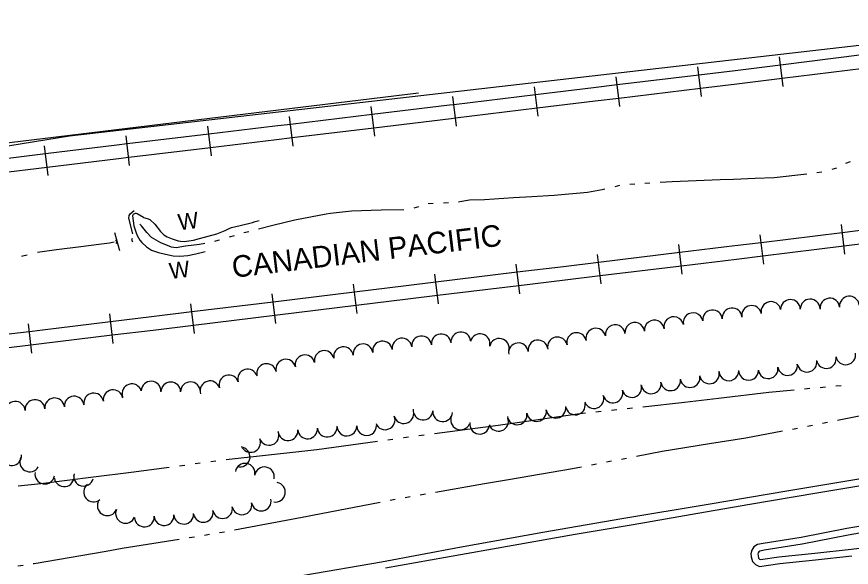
# Model space of a CAD drawing. Extents: x 589250 to 1188077, y 162953 to 363065.
# Drawn here: x 591882.9 to 592191.9, y 174605.4 to 174809.3 of the extents above; entities that cross this region are included whole.
import ezdxf

# ---------------------------------------------------------------- set-up
doc = ezdxf.new("R2010")
doc.units = 0
for name, color, linetype in [('E_DRN', 7, 'Continuous'), ('E_LAND_TreeLine_P', 7, 'Continuous'), ('E_MAP_Limits', 7, 'Continuous'), ('E_RDWY', 7, 'Continuous'), ('E_RDWY_C_and_G', 7, 'Continuous'), ('E_RDWY_Gravel', 7, 'Continuous'), ('E_RR_P', 7, 'Continuous'), ('E_RR_Text', 7, 'Continuous'), ('E_STRUCT', 7, 'Continuous'), ('E_WAL', 7, 'Continuous'), ('E_WAL_Text', 7, 'Continuous'), ('E_WTR_FlowLine', 7, 'Continuous'), ('Level 12', 7, 'Continuous')]:
    doc.layers.add(name, color=color, linetype=linetype)

msp = doc.modelspace()

# ---------------------------------------------------------------- linework, layer by layer
at = {"layer": 'E_DRN'}
for centre, radius, start, end in [((591926.97, 174735.19), 1.2, 60.0565, 166.3167), ((591919.21, 174725.84), 0.783, 318.9912, 65.2514), ((591926.26, 174726.59), 0.777, 136.6852, 242.9454)]:
    msp.add_arc(centre, radius, start, end, dxfattribs=at)
at = {"layer": 'E_LAND_TreeLine_P'}
for centre, start, end in [((592176.66, 174701.03), 1.2344, 181.2344), ((592183.94, 174701.37), 5.9652, 185.9652), ((592191.19, 174702.12), 5.9652, 185.9652), ((592154.99, 174698.67), 11.2385, 191.2385), ((592162.14, 174700.1), 11.2385, 191.2385), ((592169.36, 174700.88), 1.2344, 181.2344), ((592133.3, 174695.97), 11.4822, 191.4822), ((592140.5, 174697.02), 5.6269, 185.6269), ((592147.76, 174697.74), 5.6269, 185.6269), ((592111.73, 174692.41), 6.7718, 186.7718), ((592118.97, 174693.27), 6.7718, 186.7718), ((592126.15, 174694.51), 11.4822, 191.4822), ((592047.33, 174688.84), 5.7649, 185.7649), ((592097.32, 174690.23), 12.803, 192.803), ((592104.49, 174691.55), 6.7718, 186.7718), ((592025.57, 174686.58), 8.4831, 188.4831), ((592032.82, 174687.37), 5.7649, 185.7649), ((592040.08, 174688.11), 5.7649, 185.7649), ((592054.49, 174688.18), 346.3167, 166.3167), ((592061.58, 174686.46), 346.726, 166.726), ((592075.89, 174685.88), 8.4831, 188.4831), ((592083.1, 174687), 12.803, 192.803), ((592090.21, 174688.61), 12.803, 192.803), ((592003.93, 174683.35), 8.4831, 188.4831), ((592011.15, 174684.43), 8.4831, 188.4831), ((592018.36, 174685.5), 8.4831, 188.4831), ((592068.68, 174684.8), 8.4831, 188.4831), ((591989.66, 174680.36), 12.7704, 192.7704), ((591996.78, 174681.97), 12.7704, 192.7704), ((592182.64, 174682.68), 190.7288, 10.7288), ((592189.81, 174684.04), 190.7288, 10.7288), ((591975.44, 174677.13), 12.7704, 192.7704), ((591982.55, 174678.75), 12.7704, 192.7704), ((592168.29, 174680.08), 189.1734, 9.1734), ((592175.48, 174681.33), 190.7288, 10.7288), ((591968.44, 174675.09), 17.3083, 197.3083), ((592139.36, 174676.99), 190.8445, 10.8445), ((592146.55, 174678.1), 181.4547, 1.4547), ((592153.84, 174678.29), 181.4547, 1.4547), ((592161.09, 174678.91), 189.1734, 9.1734), ((591932.69, 174670.63), 357.69, 177.69), ((591939.98, 174670.34), 0.353, 180.353), ((591947.27, 174670.39), 0.353, 180.353), ((591954.51, 174670.75), 17.3083, 197.3083), ((591961.48, 174672.92), 17.3083, 197.3083), ((592117.8, 174673.3), 189.0991, 9.0991), ((592125, 174674.45), 189.0991, 9.0991), ((592132.2, 174675.62), 190.8445, 10.8445), ((591918.62, 174667.46), 9.6463, 189.6463), ((591925.57, 174669.65), 17.5515, 197.5515), ((592103.63, 174669.94), 196.0325, 16.0325), ((592110.64, 174671.95), 196.0325, 16.0325), ((591896.96, 174664.44), 5.0608, 185.0608), ((591904.23, 174665.08), 5.0608, 185.0608), ((591911.43, 174666.24), 9.6463, 189.6463), ((592096.65, 174667.84), 199.3234, 19.3234), ((591882.44, 174663.15), 5.2175, 185.2175), ((591889.7, 174663.8), 5.0608, 185.0608), ((592082.56, 174664.29), 189.5153, 9.5153), ((592089.75, 174665.49), 189.5153, 9.5153), ((592026.24, 174662.26), 194.0243, 14.0243), ((592033.35, 174663.6), 175.4539, 355.4539), ((592040.62, 174663.02), 175.4539, 355.4539), ((592047.25, 174659.99), 155.2381, 335.2381), ((592068.18, 174661.8), 189.8153, 9.8153), ((592075.37, 174663.04), 189.8153, 9.8153), ((592019.33, 174659.99), 202.1544, 22.1544), ((592054.32, 174658.37), 170.345, 350.345), ((592061.3, 174659.42), 200.0068, 20.0068), ((591976.34, 174654.23), 201.0274, 21.0274), ((591983.35, 174655.97), 185.1166, 5.1166), ((591990.61, 174656.62), 185.1166, 5.1166), ((591997.88, 174657.27), 185.1166, 5.1166), ((592005.15, 174657.66), 181.4339, 1.4339), ((592012.45, 174657.84), 181.4339, 1.4339), ((591969.53, 174651.61), 201.0274, 21.0274), ((591965.67, 174646.25), 253.2503, 73.2503), ((591881.1, 174646.74), 184.0052, 4.0052), ((591887.75, 174644.41), 150.8771, 330.8771), ((591967.47, 174640.23), 349.3494, 169.3494), ((591893.33, 174639.9), 170.2283, 350.2283), ((591907.71, 174639.11), 165.0979, 345.0979), ((591974.64, 174638.88), 349.3494, 169.3494), ((591900.52, 174638.89), 187.1958, 7.1958), ((591978.71, 174633.18), 260.0481, 80.0481), ((591911.44, 174633.25), 129.6424, 309.6424), ((591973.48, 174629.9), 190.9726, 10.9726), ((591916.49, 174628.17), 157.3017, 337.3017), ((591959.16, 174627.12), 190.9726, 10.9726), ((591966.32, 174628.51), 190.9726, 10.9726), ((591923.22, 174625.35), 157.3017, 337.3017), ((591937.47, 174624.54), 183.9669, 3.9669), ((591944.75, 174625.04), 183.9669, 3.9669), ((591952, 174625.73), 190.9726, 10.9726), ((591930.2, 174624.03), 183.9669, 3.9669)]:
    msp.add_arc(centre, 3.65, start, end, dxfattribs=at)
at = {"layer": 'E_MAP_Limits'}
for p, q in [((592288.04, 174809.26), (591902.43, 174765.07)), ((591902.43, 174765.07), (591727.11, 174736.15))]:
    msp.add_line(p, q, dxfattribs=at)
at = {"layer": 'E_RDWY'}
for p, q in [((592199.66, 174636.31), (592179.15, 174632.85)), ((592179.15, 174632.85), (592154.37, 174628.58)), ((592154.37, 174628.58), (592135.1, 174625.35)), ((592135.1, 174625.35), (592111.17, 174621.16)), ((592111.17, 174621.16), (592089.73, 174617.52)), ((592089.73, 174617.52), (592066.73, 174613.49)), ((592066.73, 174613.49), (592041.64, 174609.06)), ((592041.64, 174609.06), (592019.5, 174605.11))]:
    msp.add_line(p, q, dxfattribs=at)
at = {"layer": 'E_RDWY_C_and_G'}
for p, q in [((592209.3, 174623.07), (592190.26, 174619.72)), ((592190.22, 174619.71), (592173.31, 174616.45)), ((592209.73, 174620.61), (592190.69, 174617.26)), ((592173.31, 174616.45), (592159.27, 174614.15)), ((592190.69, 174617.26), (592173.75, 174613.99)), ((592155.86, 174612.92), (592155.1, 174611.77)), ((592157.12, 174613.77), (592155.86, 174612.92)), ((592159.27, 174614.15), (592157.12, 174613.77)), ((592173.75, 174613.99), (592159.69, 174611.68)), ((592178.35, 174610.58), (592191.8, 174612.08)), ((592191.8, 174612.08), (592210.37, 174614.28)), ((592155.1, 174611.77), (592154.73, 174610.43)), ((592154.73, 174610.43), (592154.88, 174609.28)), ((592154.88, 174609.28), (592155.27, 174607.51)), ((592157.41, 174610.72), (592157.27, 174610.25)), ((592157.27, 174610.25), (592157.35, 174609.71)), ((592157.35, 174609.71), (592157.55, 174608.77)), ((592157.67, 174611.13), (592157.41, 174610.72)), ((592158.08, 174611.4), (592157.67, 174611.13)), ((592159.69, 174611.68), (592158.08, 174611.4)), ((592158.3, 174608.24), (592165.09, 174609.22)), ((592165.09, 174609.22), (592178.35, 174610.58)), ((592178.61, 174608.1), (592192.09, 174609.6)), ((592155.27, 174607.51), (592156.42, 174606.37)), ((592156.42, 174606.37), (592157.89, 174605.65)), ((592157.55, 174608.77), (592157.89, 174608.44)), ((592157.89, 174608.44), (592158.3, 174608.24)), ((592157.89, 174605.65), (592165.4, 174606.74)), ((592165.4, 174606.74), (592178.61, 174608.1))]:
    msp.add_line(p, q, dxfattribs=at)
at = {"layer": 'E_RDWY_Gravel'}
for p, q in [((592199.98, 174638.97), (592168.82, 174633.72)), ((592168.82, 174633.72), (592138.91, 174628.64)), ((592168.82, 174633.72), (592168.82, 174633.72)), ((592138.91, 174628.64), (592106.98, 174623.39)), ((592106.98, 174623.39), (592077.76, 174618.31)), ((592077.76, 174618.31), (592046.91, 174612.68)), ((592046.91, 174612.68), (592017.93, 174607.26)), ((592017.93, 174607.26), (591989.19, 174602.34))]:
    msp.add_line(p, q, dxfattribs=at)
at = {"layer": 'E_RR_P'}
for p, q in [((592166.71, 174783.36), (592165.36, 174794.34)), ((592195.89, 174795.08), (592165.73, 174791.35)), ((592165.72, 174791.35), (592148.88, 174789.26)), ((592136.44, 174779.67), (592135.13, 174790.65)), ((592148.88, 174789.26), (592135.49, 174787.65)), ((592196.51, 174790.08), (592166.35, 174786.35)), ((592106.2, 174776.03), (592104.89, 174787.01)), ((592135.49, 174787.65), (592105.25, 174784.02)), ((592166.34, 174786.35), (592149.49, 174784.27)), ((592075.97, 174772.37), (592074.65, 174783.35)), ((592096.51, 174782.97), (592075.01, 174780.36)), ((592105.25, 174784.02), (592096.51, 174782.97)), ((592136.09, 174782.66), (592105.85, 174779.02)), ((592149.49, 174784.27), (592136.09, 174782.66)), ((592045.74, 174768.69), (592044.41, 174779.67)), ((592075.01, 174780.36), (592044.77, 174776.68)), ((592105.85, 174779.02), (592097.11, 174777.97)), ((592015.49, 174765.03), (592014.17, 174776.01)), ((592043.18, 174776.48), (592014.53, 174773.02)), ((592044.77, 174776.68), (592043.18, 174776.48)), ((592097.11, 174777.97), (592075.62, 174775.36)), ((592014.53, 174773.02), (591984.29, 174769.37)), ((592075.61, 174775.36), (592045.38, 174771.68)), ((591985.25, 174761.38), (591983.93, 174772.36)), ((592043.79, 174771.49), (592015.14, 174768.02)), ((592045.38, 174771.68), (592043.79, 174771.49)), ((591954.99, 174757.75), (591953.69, 174768.74)), ((591978.51, 174768.67), (591954.05, 174765.74)), ((591984.29, 174769.37), (591978.51, 174768.67)), ((592015.13, 174768.02), (591984.9, 174764.37)), ((591924.75, 174754.14), (591923.44, 174765.12)), ((591954.04, 174765.74), (591923.8, 174762.13)), ((591979.11, 174763.67), (591954.64, 174760.75)), ((591984.89, 174764.37), (591979.11, 174763.67)), ((591894.53, 174750.47), (591893.2, 174761.45)), ((591919.98, 174761.67), (591893.56, 174758.46)), ((591923.8, 174762.13), (591919.98, 174761.67)), ((591954.64, 174760.75), (591924.4, 174757.13)), ((591893.56, 174758.46), (591866.36, 174755.14)), ((591920.58, 174756.68), (591894.17, 174753.46)), ((591924.39, 174757.13), (591920.58, 174756.68)), ((591894.17, 174753.46), (591866.98, 174750.14)), ((592217.1, 174732.82), (592188.56, 174729.29)), ((592189.54, 174721.34), (592188.2, 174732.27)), ((592159.45, 174717.63), (592158.11, 174728.55)), ((592188.56, 174729.29), (592158.48, 174725.58)), ((592217.72, 174727.84), (592189.18, 174724.32)), ((592129.33, 174713.96), (592128.02, 174724.89)), ((592148.75, 174724.38), (592128.38, 174721.91)), ((592158.47, 174725.58), (592148.75, 174724.38)), ((592189.17, 174724.32), (592159.09, 174720.6)), ((592099.24, 174710.32), (592097.92, 174721.25)), ((592128.38, 174721.91), (592098.28, 174718.27)), ((592159.09, 174720.6), (592149.36, 174719.4)), ((592069.15, 174706.67), (592067.82, 174717.59)), ((592098.28, 174718.27), (592085.32, 174716.7)), ((592149.36, 174719.4), (592128.98, 174716.94)), ((592068.18, 174714.62), (592038.09, 174710.95)), ((592085.32, 174716.7), (592068.19, 174714.62)), ((592128.98, 174716.94), (592098.88, 174713.3)), ((592038.09, 174710.95), (592027.1, 174709.61)), ((592039.05, 174703), (592037.73, 174713.92)), ((592085.93, 174711.73), (592068.79, 174709.64)), ((592098.88, 174713.3), (592085.93, 174711.73)), ((592008.96, 174699.33), (592007.63, 174710.26)), ((592027.1, 174709.61), (592008, 174707.28)), ((592068.79, 174709.64), (592038.7, 174705.97)), ((591978.87, 174695.66), (591977.54, 174706.59)), ((592007.99, 174707.28), (591978.88, 174703.73)), ((592038.69, 174705.97), (592027.71, 174704.64)), ((591948.78, 174691.97), (591947.45, 174702.9)), ((591977.9, 174703.61), (591947.81, 174699.92)), ((591978.88, 174703.73), (591977.9, 174703.61)), ((592008.6, 174702.31), (591979.48, 174698.76)), ((592027.71, 174704.64), (592008.6, 174702.31)), ((591918.67, 174688.3), (591917.36, 174699.23)), ((591947.81, 174699.92), (591932.81, 174698.08)), ((591978.51, 174698.64), (591948.42, 174694.95)), ((591979.48, 174698.76), (591978.51, 174698.64)), ((591888.58, 174684.67), (591887.25, 174695.59)), ((591917.71, 174696.26), (591891.48, 174693.09)), ((591932.81, 174698.08), (591917.72, 174696.26)), ((591887.61, 174692.62), (591857.52, 174688.95)), ((591891.48, 174693.09), (591887.62, 174692.62)), ((591933.42, 174693.11), (591918.32, 174691.28)), ((591948.42, 174694.95), (591933.42, 174693.11)), ((591918.31, 174691.28), (591892.08, 174688.11)), ((591888.22, 174687.64), (591858.13, 174683.97)), ((591892.08, 174688.11), (591888.23, 174687.64))]:
    msp.add_line(p, q, dxfattribs=at)
at = {"layer": 'E_STRUCT'}
for p, q in [((591929.9, 174734.94), (591927.57, 174736.23)), ((591925.81, 174735.47), (591926.34, 174731.8))]:
    msp.add_line(p, q, dxfattribs=at)
at = {"layer": 'E_WAL'}
for p, q in [((591924.51, 174734.61), (591924.55, 174735.63)), ((591924.55, 174735.63), (591924.96, 174736.28)), ((591924.96, 174736.28), (591926.44, 174737.54)), ((591925.89, 174728.86), (591924.51, 174734.61)), ((591929.9, 174734.94), (591931.25, 174734.53)), ((591931.25, 174734.53), (591932.27, 174734.12)), ((591932.27, 174734.12), (591934.09, 174732.46)), ((591965.71, 174731.95), (591970.25, 174733.05)), ((591970.25, 174733.05), (591971.22, 174733.38)), ((591971.22, 174733.38), (591972.75, 174733.81)), ((591926.34, 174731.8), (591927.06, 174729.63)), ((591927.06, 174729.63), (591927.58, 174728.19)), ((591934.09, 174732.46), (591936.2, 174729.68)), ((591936.2, 174729.68), (591937.46, 174728.53)), ((591957.04, 174728.84), (591960.1, 174730.06)), ((591960.1, 174730.06), (591961.53, 174730.81)), ((591961.53, 174730.81), (591962.51, 174731.15)), ((591962.51, 174731.15), (591965.71, 174731.95)), ((591919.1, 174729.32), (591921, 174722.74)), ((591927.58, 174728.19), (591928.52, 174726.48)), ((591928.52, 174726.48), (591929.31, 174725.69)), ((591937.46, 174728.53), (591938.67, 174727.7)), ((591938.67, 174727.7), (591940.44, 174727.02)), ((591940.44, 174727.02), (591942.77, 174726.29)), ((591942.77, 174726.29), (591943.61, 174726.11)), ((591946.61, 174726.22), (591948.33, 174726.55)), ((591948.33, 174726.55), (591950.6, 174727.08)), ((591950.6, 174727.08), (591957.04, 174728.84)), ((591929.31, 174725.69), (591930.95, 174724.08)), ((591930.95, 174724.08), (591932.86, 174722.84)), ((591943.61, 174726.11), (591944.94, 174725.98)), ((591944.94, 174725.98), (591946.61, 174726.22)), ((591932.86, 174722.84), (591935.47, 174721.92)), ((591935.47, 174721.92), (591938.07, 174721.29)), ((591938.07, 174721.29), (591940.91, 174720.66)), ((591940.91, 174720.66), (591943.32, 174720.63)), ((591943.32, 174720.63), (591946.24, 174720.88)), ((591946.24, 174720.88), (591949.26, 174721.41)), ((591949.26, 174721.41), (591952.74, 174722.31))]:
    msp.add_line(p, q, dxfattribs=at)
at = {"layer": 'E_WTR_FlowLine'}
for p, q in [((592191.46, 174755.57), (592189.71, 174754.9)), ((592180.98, 174751.75), (592179.12, 174751.49)), ((592186.43, 174753.13), (592184.62, 174752.63)), ((592125.55, 174748.13), (592121.09, 174747.87)), ((592143.32, 174748.84), (592125.55, 174748.13)), ((592148.28, 174749.02), (592143.32, 174748.84)), ((592156.3, 174749.32), (592148.28, 174749.02)), ((592163.29, 174749.56), (592156.3, 174749.32)), ((592175.4, 174750.98), (592163.29, 174749.56)), ((592099.61, 174745.17), (592094.23, 174744.14)), ((592100.65, 174745.42), (592099.61, 174745.17)), ((592106.13, 174746.71), (592104.31, 174746.28)), ((592111.73, 174747.26), (592109.86, 174747.1)), ((592117.35, 174747.65), (592115.47, 174747.55)), ((592066.89, 174742.18), (592056.11, 174741.51)), ((592073.63, 174742.58), (592066.89, 174742.18)), ((592081.86, 174743.07), (592073.63, 174742.58)), ((592094.23, 174744.14), (592081.86, 174743.07)), ((592031.71, 174738.91), (592030.77, 174738.56)), ((592037.14, 174740.08), (592035.27, 174740.01)), ((592042.76, 174740.36), (592040.89, 174740.23)), ((592046.93, 174740.66), (592046.5, 174740.63)), ((592050.52, 174741.28), (592046.93, 174740.66)), ((592056.11, 174741.51), (592050.52, 174741.28)), ((591997.44, 174736.16), (591985.88, 174733.89)), ((591999.07, 174736.34), (591997.44, 174736.16)), ((592006.82, 174737.21), (591999.07, 174736.34)), ((592017.8, 174737.68), (592006.82, 174737.21)), ((592026.22, 174737.73), (592017.8, 174737.68)), ((592030.77, 174738.56), (592029.91, 174738.39)), ((591985.88, 174733.89), (591978.3, 174732.05)), ((591929.18, 174731.77), (591928.54, 174732.4)), ((591931.09, 174729.41), (591929.18, 174731.77)), ((591932.83, 174727.53), (591931.09, 174729.41)), ((591968.85, 174729.66), (591967.03, 174729.2)), ((591978.3, 174732.05), (591972.49, 174730.58)), ((591936.32, 174725.5), (591932.83, 174727.53)), ((591957.37, 174726.33), (591956.22, 174726.08)), ((591958.04, 174726.53), (591957.37, 174726.33)), ((591963.43, 174728.16), (591961.63, 174727.61)), ((591897.73, 174723.1), (591906.63, 174724.14)), ((591906.63, 174724.14), (591913.38, 174725.01)), ((591913.38, 174725.01), (591917.33, 174725.52)), ((591917.33, 174725.52), (591918.98, 174725.86)), ((591940.28, 174723.94), (591936.32, 174725.5)), ((591942.01, 174723.64), (591940.28, 174723.94)), ((591945.41, 174724.26), (591942.01, 174723.64)), ((591950.59, 174724.89), (591945.41, 174724.26)), ((591952.54, 174725.3), (591950.59, 174724.89)), ((591884.87, 174720.62), (591885.22, 174720.71)), ((591885.22, 174720.71), (591886.78, 174721.1)), ((591890.61, 174722.05), (591890.65, 174722.06)), ((591890.65, 174722.06), (591897.73, 174723.1)), ((592170.69, 174671.01), (592161.36, 174670.16)), ((592176.5, 174671.54), (592174.56, 174671.36)), ((592182.3, 174672.07), (592180.37, 174671.89)), ((592188.1, 174672.6), (592186.17, 174672.42)), ((592142.7, 174667.88), (592130.18, 174666.35)), ((592161.36, 174670.16), (592142.7, 174667.88)), ((592130.18, 174666.35), (592114.71, 174664.7)), ((592091.34, 174662.21), (592065.56, 174658.57)), ((592093.46, 174662.43), (592091.34, 174662.21)), ((592099.26, 174663.05), (592097.33, 174662.84)), ((592105.05, 174663.67), (592103.12, 174663.46)), ((592110.85, 174664.29), (592108.92, 174664.08)), ((592186.82, 174659.86), (592207.34, 174664.08)), ((592065.56, 174658.57), (592059.33, 174657.69)), ((592181.27, 174658.72), (592183.12, 174659.1)), ((592059.33, 174657.69), (592037.64, 174654.82)), ((592152.85, 174653.36), (592166.41, 174655.9)), ((592170.13, 174656.59), (592171.98, 174656.94)), ((592175.7, 174657.63), (592177.56, 174657.98)), ((592022.23, 174652.77), (592020.31, 174652.51)), ((592026.21, 174653.31), (592026.08, 174653.29)), ((592028.01, 174653.55), (592026.21, 174653.31)), ((592033.79, 174654.31), (592031.86, 174654.06)), ((592139.4, 174651.18), (592152.85, 174653.36)), ((592016.46, 174651.98), (591994.06, 174648.93)), ((592121.87, 174648.34), (592139.4, 174651.18)), ((591988.53, 174648.31), (591960.54, 174645.16)), ((591994.06, 174648.93), (591988.53, 174648.31)), ((592112.39, 174646.52), (592121.87, 174648.34)), ((591945.13, 174643.11), (591943.2, 174642.85)), ((591950.9, 174643.9), (591948.98, 174643.64)), ((591956.68, 174644.68), (591954.76, 174644.42)), ((592095.67, 174643.33), (592097.53, 174643.68)), ((592101.24, 174644.39), (592103.1, 174644.75)), ((592106.82, 174645.46), (592108.67, 174645.81)), ((591925.29, 174640.43), (591911.42, 174638.72)), ((591939.35, 174642.33), (591925.29, 174640.43)), ((592064.95, 174637.9), (592088.71, 174641.99)), ((592088.71, 174641.99), (592091.96, 174642.61)), ((591911.42, 174638.72), (591891.89, 174636.32)), ((592056.13, 174636.38), (592064.95, 174637.9)), ((591891.89, 174636.32), (591883.45, 174635.38)), ((592037.94, 174633.2), (592056.13, 174636.38)), ((592021.19, 174630.2), (592023.05, 174630.56)), ((592026.76, 174631.25), (592028.63, 174631.57)), ((592032.35, 174632.23), (592034.21, 174632.55)), ((591992.45, 174624.72), (592017.47, 174629.49)), ((591963.6, 174619.27), (591990.54, 174624.36)), ((591990.54, 174624.36), (591992.45, 174624.72)), ((591958.03, 174618.22), (591959.89, 174618.57)), ((591922.02, 174612.44), (591943.1, 174615.81)), ((591946.83, 174616.41), (591948.7, 174616.71)), ((591952.43, 174617.3), (591954.3, 174617.6)), ((591916.04, 174611.41), (591922.02, 174612.44)), ((591889.44, 174606.83), (591916.03, 174611.41)), ((591883.41, 174605.88), (591885.28, 174606.17)), ((591889.02, 174606.76), (591889.44, 174606.83))]:
    msp.add_line(p, q, dxfattribs=at)
at = {"layer": 'Level 12'}
msp.add_lwpolyline([(591157.73, 174674.88), (592031.69, 174781.12)], dxfattribs=at)

# ---------------------------------------------------------------- texts
at = {"layer": 'E_RR_Text'}
msp.add_text('CANADIAN PACIFIC', height=8, rotation=6.8307, dxfattribs=at).set_placement((591963.09, 174712.54))
at = {"layer": 'E_WAL_Text'}
for p in [(591943.02, 174730.16), (591939.79, 174712.09)]:
    msp.add_text('W', height=6, rotation=7.1543, dxfattribs=at).set_placement(p)

doc.saveas('drawing.dxf')
